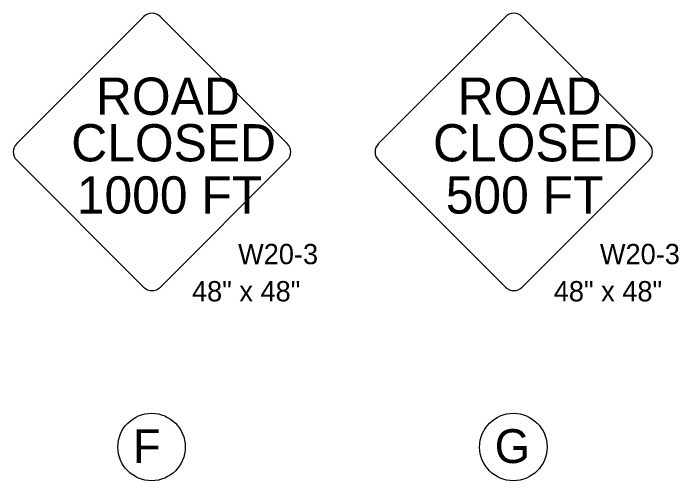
# Model space of a CAD drawing. Extents: x 2157572 to 5059327, y 715220 to 1674494.
# Drawn here: x 2166241 to 2167197, y 719491 to 720163 of the extents above; entities that cross this region are included whole.
import ezdxf

# ---------------------------------------------------------------- set-up
doc = ezdxf.new("R2010")
doc.units = 0
for name, color, linetype in [('Exist Cultural Church Label', 7, 'Continuous'), ('Map Preparation County Base Legend Highway Garage or Maintenance Office', 7, 'Continuous'), ('Map Preparation County Base Positioning Point', 7, 'Continuous')]:
    doc.layers.add(name, color=color, linetype=linetype)

msp = doc.modelspace()

# ---------------------------------------------------------------- linework, layer by layer
at = {"layer": 'Exist Cultural Church Label'}
for centre in [(2166440.01, 719539.79), (2166959.73, 719539.79)]:
    msp.add_circle(centre, 48.43, dxfattribs=at)
at = {"layer": 'Map Preparation County Base Legend Highway Garage or Maintenance Office'}
for centre in [(2166440.01, 719539.79), (2166959.73, 719539.79)]:
    msp.add_circle(centre, 48.43, dxfattribs=at)
at = {"layer": 'Map Preparation County Base Positioning Point'}
for points in [[(2166246.39, 719975.93), (2166428.66, 720158.19)], [(2166452.73, 720158.18), (2166634.98, 719975.93)], [(2166766.1, 719975.93), (2166948.37, 720158.19)], [(2166972.44, 720158.18), (2167154.69, 719975.93)], [(2166428.66, 719769.6), (2166246.39, 719951.85)], [(2166634.98, 719951.85), (2166452.73, 719769.6)], [(2166948.37, 719769.6), (2166766.1, 719951.85)], [(2167154.69, 719951.85), (2166972.44, 719769.6)]]:
    msp.add_lwpolyline(points, dxfattribs=at)
for centre, start, end in [((2166440.69, 720146.15), 44.98697, 135), ((2166960.4, 720146.15), 44.98697, 135), ((2166258.43, 719963.89), 135, 225), ((2166622.95, 719963.89), 315, 45), ((2166778.14, 719963.89), 135, 225), ((2167142.66, 719963.89), 315, 45), ((2166440.69, 719781.63), 225, 315), ((2166960.4, 719781.63), 225, 315)]:
    msp.add_arc(centre, 17.02, start, end, dxfattribs=at)

# ---------------------------------------------------------------- texts
at = {"layer": 'Exist Cultural Church Label'}
for s, p in [('F', (2166413.21, 719516.72)), ('G', (2166932.92, 719516.72))]:
    msp.add_text(s, height=48.63, dxfattribs=at).set_placement(p)
at = {"layer": 'Map Preparation County Base Positioning Point'}
for s, height, p in [('ROAD', 53.496, (2166360.06, 720017.29)), ('ROAD', 53.496, (2166879.77, 720017.29)), ('CLOSED', 53.496, (2166324.6, 719950.32)), ('CLOSED', 53.496, (2166844.31, 719950.32)), ('1000 FT', 53.496, (2166332.58, 719875.32)), ('500 FT', 53.496, (2166862.59, 719875.32)), ('W20-3', 29.18, (2166564.31, 719802.55)), ('W20-3', 29.18, (2167084.03, 719802.55)), ('48" x 48"', 29.18, (2166498.05, 719749.08)), ('48" x 48"', 29.18, (2167017.76, 719749.08))]:
    msp.add_text(s, height=height, dxfattribs=at).set_placement(p)

doc.saveas('drawing.dxf')
